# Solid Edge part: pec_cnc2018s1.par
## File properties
Author: LABUSIG
Template: iso metric part.par
Last saved by: LABUSIG
Revision: 26
Application: Solid Edge
Username: LABUSIG
Accuracy: 0.990
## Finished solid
Body 1: solid body, 15 faces, 21 edges, 8 vertices.
  Faces by surface: cylinder 4, plane 4, cone 3, spline 3, torus 1
  Edges by curve: circle 11, intersection 6, spline 4
Bounding box of the edges (mm; curved faces can reach further): 58.000 x 46.000 x 46.000, from (-58, -23, -23) to (0, 23, 23).
Cylindrical faces by radius (mm): R13.5 x1, R15 x2, R23 x1
Conical faces (half-angle, radius in mm at the cone's reference point): 45 deg R13.5 x1, 45 deg R23 x1, 52 deg R15.7687 x1
Toroidal faces (ring radius, tube radius in mm): R17 r2 x1
Planar faces by outward normal: +x 2, -x 2
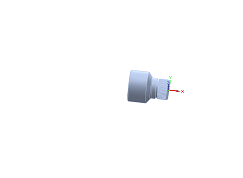
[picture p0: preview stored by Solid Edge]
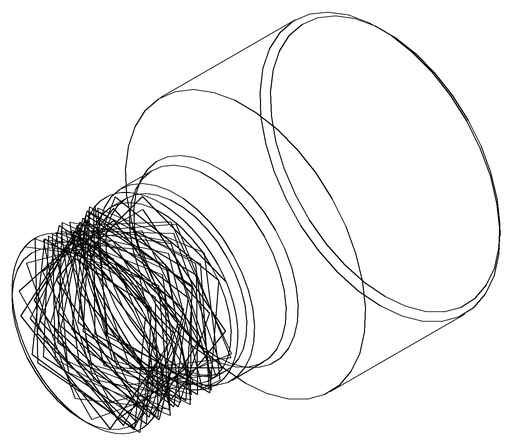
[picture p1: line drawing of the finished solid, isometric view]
